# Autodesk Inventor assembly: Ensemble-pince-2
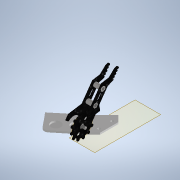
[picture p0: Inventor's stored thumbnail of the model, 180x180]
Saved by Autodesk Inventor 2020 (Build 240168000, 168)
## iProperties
Created: 2021-10
Part Number: Ensemble-pince-2
Document SubType Name: Assembly
Designer: bruno
Author: bruno
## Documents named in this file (5)
- C:\Users\bruno\OneDrive\Bureau\Robot-Inventor\Robot-equillibrage\Ensemble-pince-2.iam
- C:\Users\bruno\OneDrive\Bureau\Robot-Inventor\Robot-equillibrage\Ensemble-doigt-2.iam
- C:\Users\bruno\OneDrive\Bureau\Robot-Inventor\Robot-equillibrage\pince-2.ipt
- C:\Users\bruno\Documents\Inventor\Content Center Files\R2020\fr-FR\ANSI B18.6.7M(01)\ANSI B18.6.7M - M3x0,5 x 5(5).ipt
- C:\Users\bruno\OneDrive\Bureau\Robot-Inventor\Robot-equillibrage\pince-uhl-D.ipt
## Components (6 placed, 4 different names)
1. Ensemble-doigt-2:1 [sub-assembly] — Logement:1, Logement:2, Logement:3, Logement:4
2. pince-2:1 — Logement:1, Logement:2, Logement:5, Logement:6
3. Vis à tête tronconique à empreinte cruciforme - Type IA - Métrique M3x0,5 x 5:1 — Logement:6
4. Vis à tête tronconique à empreinte cruciforme - Type IA - Métrique M3x0,5 x 5:2 — Logement:5
5. Vis à tête tronconique à empreinte cruciforme - Type IA - Métrique M3x0,5 x 5:3
6. pince-uhl-D:1 — Logement:3, Logement:4
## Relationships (6: Insert 6)
- Logement:1 [Insert]: Ensemble-doigt-2:1 ↔ pince-2:1
- Logement:2 [Insert]: Ensemble-doigt-2:1 ↔ pince-2:1
- Logement:3 [Insert]: Ensemble-doigt-2:1 ↔ pince-uhl-D:1
- Logement:4 [Insert]: Ensemble-doigt-2:1 ↔ pince-uhl-D:1
- Logement:5 [Insert]: pince-2:1 ↔ Vis à tête tronconique à empreinte cruciforme - Type IA - Métrique M3x0,5 x 5:2
- Logement:6 [Insert]: pince-2:1 ↔ Vis à tête tronconique à empreinte cruciforme - Type IA - Métrique M3x0,5 x 5:1
